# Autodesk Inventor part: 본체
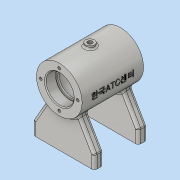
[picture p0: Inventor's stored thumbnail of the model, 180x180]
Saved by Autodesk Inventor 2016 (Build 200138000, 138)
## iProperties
Created: 2018-05
Part Number: 본체
Material: 알루미늄 6061
Document SubType Name: Modeling
Designer: 301-08
Density: 2.7 g/cm^3
Appearance: 알루미늄 - 평지
Mass: 317.681 g
Surface Area: 375.844 cm^2
Volume: 117.66 cm^3
Author: 301-08
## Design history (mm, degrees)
node "작업 평면1"
sketch "스케치1"
  geometry: 1 further point
sketch "스케치2"
  geometry: L1 (35, 0)-(-35, 0); L2 (35, 0)-(35, 15); L3 (35, 15)-(6.132, 65); L4 (6.132, 65)-(-6.132, 65); L5 (-6.132, 65)-(-35, 15); L6 (-35, 15)-(-35, 0); 2 further points
  constraints: 12 end point, 1 coincident, 1 horizontal, 1 midpoint, 1 parallel, 1 perpendicular, 1 vertical
  dimensions: "d1" = 70 distance of L1.start L1.end; "d2" = 15 distance of L1.start L2.end; "d3" = 15 distance of L5.end L1.end; "d4" = 30 deg angle of L2 L3; "d5" = 30 deg angle of L6 L5; "d6" = 65 distance between parallel lines of L1 L4
extrude "돌출1" new body sketch "스케치2" distance "d7" = 10; taper "d8" = 0 deg
sketch "스케치3"
  geometry: L1 (-35, 65)-(35, 65); L2 (0, 0)-(0, 29.935); L3 (-35, 65)-(-35, 91); L4 (-35, 91)-(35, 91); L5 (35, 91)-(35, 65); 1 further point
  constraints: 10 end point, 2 perpendicular, 2 vertical, 1 horizontal, 1 midpoint, 1 point on line
  dimensions: "d9" = 70 distance of L1.start L1.end; "d10" = 65 distance from line of L2.start L1; "d11" = 52 diameter of L4 L1
revolve "회전1" sketch "스케치3" stored, may be unused: angle "d12" = 90 deg
sketch "스케치4"
  geometry: L1 (-35, 39)-(-35, 91) reference; L2 (-35, 65)-(35, 65); L3 (35, 39)-(35, 91) reference; L4 (-35, 65)-(-35, 81); L5 (-35, 81)-(-23, 81); L6 (-23, 81)-(-23, 79); L7 (-23, 79)-(-21, 79); L8 (-21, 79)-(-21, 86); L9 (-21, 86)-(21, 86); L10 (21, 86)-(21, 79); L11 (21, 79)-(23, 79); L12 (23, 79)-(23, 81); L13 (23, 81)-(35, 81); L14 (35, 81)-(35, 65); 1 further point
  constraints: 24 end point, 8 perpendicular, 2 midpoint, 2 point on line, 1 collinear, 1 horizontal
  dimensions: "d13" = 65 distance from line of point (0, 0) L2 (derived); "d14" = 32 diameter of L5 L2; "d15" = 28 diameter of L7 L2; "d16" = 42 diameter of L9 L2; "d17" = 12 distance of L4.end L5.end; "d18" = 2 distance of L6.end L7.end; "d19" = 42 distance of L8.end L9.end; "d20" = 2 distance of L10.end L11.end; "d21" = 12 distance of L12.end L13.end (derived); "d22" = 32 diameter of L13 L2; "d23" = 28 diameter of L11 L2
revolve "회전2" sketch "스케치4" stored, may be unused: angle "d24" = 90 deg
node "작업 평면2"
sketch "스케치5"
  geometry: L1 (26, -35)-(-26, -35) reference; C1 r 5 at (0, 0); 1 further point
  constraints: 1 centre point, 1 coincident
  dimensions: "d26" = 10 diameter of C1; "d27" = 35 distance from line of L1 C1.centre (derived)
extrude "돌출2" join sketch "스케치5" stored distance "d28" = 10; taper "d29" = 0 deg
sketch "스케치6"
  geometry: L1 (0, 65)-(17.273, 17.542); L2 (17.273, 17.542)-(0, 65); L3 (0, 0)-(0, 65); L4 (35, 0)-(-35, 0) reference; 1 further point
  constraints: 6 end point, 1 collinear, 1 perpendicular, 1 point on line, 2 other
  dimensions: "d30" = 20 deg angle of L3 L1
node "작업 평면3"
sketch "스케치7"
  geometry: C1 r 6 at (0, 0); 2 further points
  constraints: 1 centre point, 1 coincident, 1 other
  dimensions: "d31" = 12 diameter of C1
extrude "돌출3" join sketch "스케치7" stored distance "d32" = 6; taper "d33" = 0 deg
hole "구멍1" diameter "d36" = 5.188; stored, may be unused: countersink angle "d40" = 90 deg, drill point angle "d42" = 118 deg; dims "d34" = 10, "d35" = 10, "d37" = 12, "d38" = 4, "d39" = 2, "d41" = 16
hole "구멍2" diameter "d45" = 5.188; stored, may be unused: countersink angle "d49" = 90 deg, drill point angle "d51" = 118 deg; dims "d43" = 10, "d44" = 10, "d46" = 12, "d47" = 4, "d48" = 2, "d50" = 16
fillet "모깎기1" dims "d52" = 2
sketch "스케치8"
  geometry: L1 (0, 21)-(0, 0); C1 r 21 at (0, 0) reference; 2 further points
  constraints: 2 end point, 1 vertical, 1 other
  dimensions: "d53" = 21 distance of point (0, 0) L1.start
hole "구멍3" sketch "스케치8" at (0, 21) diameter "d54" = 3.242; stored, may be unused: countersink angle "d58" = 90 deg, drill point angle "d60" = 118 deg; dims "d55" = 8, "d56" = 4, "d57" = 2, "d59" = 10
sketch "스케치9"
  geometry: 1 further point
sketch "스케치10"
  geometry: 2 further points
  dimensions: "d64" = 25 vertical distance of point (20, -25) point (0, 0); "d65" = 20 horizontal distance of point (0, 0) point (20, -25)
hole "구멍4" sketch "스케치10" at (20, -25) diameter "d66" = 4.134; stored, may be unused: countersink angle "d70" = 90 deg, drill point angle "d72" = 118 deg; dims "d67" = 8, "d68" = 4, "d69" = 2, "d71" = 10
node "작업 평면4"
sketch "스케치11"
  geometry: L1 (-35, -26)-(-35, 26) reference; L2 (-35, 26)-(35, 26) reference; 2 further points
  constraints: 1 other
  dimensions: "d79" = 35 distance from line of L1 point (0, 0); "d80" = 26 distance from line of point (0, 0) L2
feature "엠보싱1" sketch "스케치11" dims "d1" = 70, "d2" = 15, "d3" = 15, "d4" = 30 deg, "d5" = 30 deg, "d6" = 65, "d81" = 0.5, "d82" = 0
fillet "모깎기2" dims "d83" = 3
chamfer "모따기1" distance "d84" = 1; stored, may be unused: second distance "d85" = 2, angle "d86" = 45 deg
fillet "모깎기3" dims "d87" = 3
fillet "모깎기4" dims "d88" = 0.3
node "솔리드1"
mirror "대칭1"
pattern_circular "원형 패턴1" dims angle "d62" = 360 deg
mirror "대칭2"
pattern_linear "직사각형 패턴1" dims "d75" = 40
other parameters: "d25" = 94
